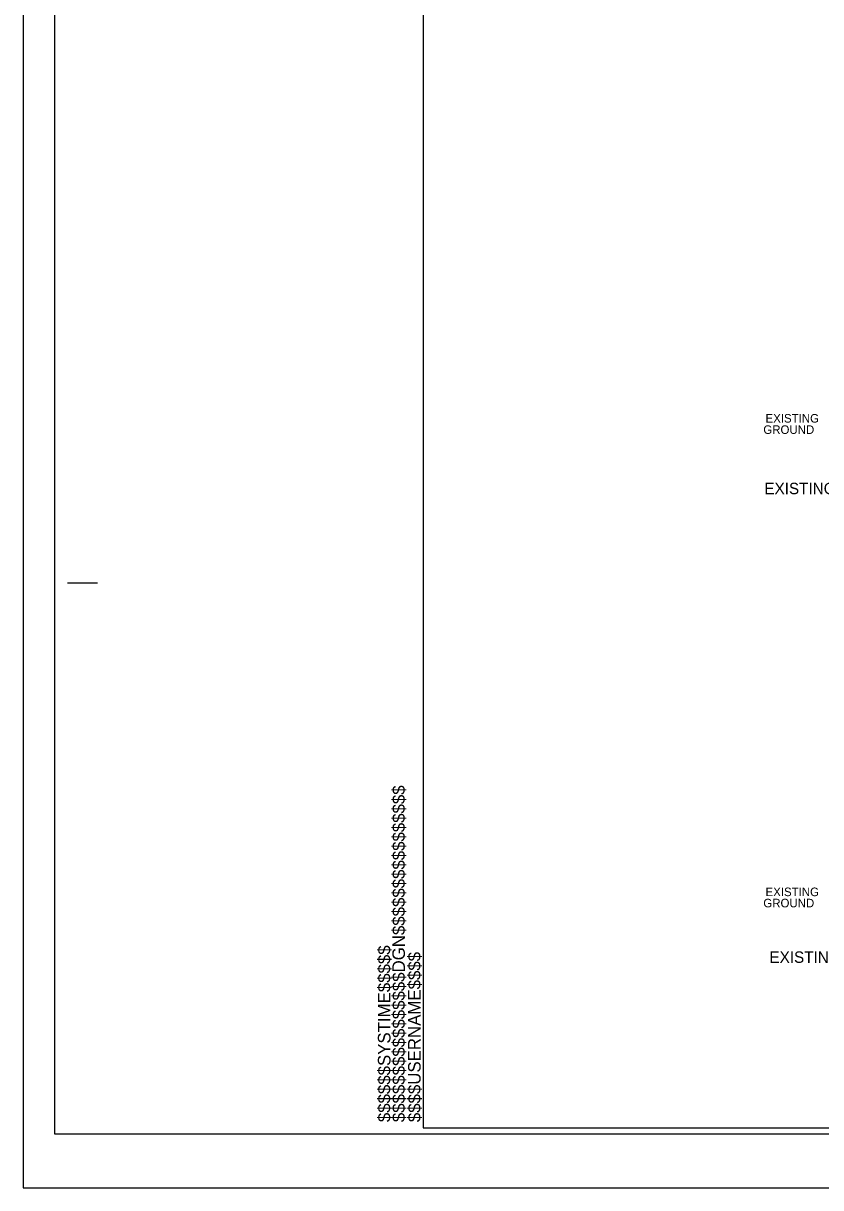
# Model space of a CAD drawing. Extents: x 1022283 to 1026986, y 174822 to 180471.
# Drawn here: x 1022283 to 1023116, y 177721 to 178936 of the extents above; entities that cross this region are included whole.
import ezdxf

# ---------------------------------------------------------------- set-up
doc = ezdxf.new("R2010")
doc.units = 0
for name, color, linetype in [('Sheet Cutting Line CELL', 7, 'Continuous'), ('Sheet Plot Border Inside CELL', 7, 'Continuous'), ('Sheet Plot Border Outside CELL', 7, 'Continuous'), ('Sheet Typical CELL', 7, 'Continuous'), ('Typical Slope Point Local CELL', 7, 'Continuous'), ('Typical Text General CELL', 7, 'Continuous')]:
    doc.layers.add(name, color=color, linetype=linetype)

msp = doc.modelspace()

# ---------------------------------------------------------------- linework, layer by layer
at = {"layer": 'Sheet Cutting Line CELL'}
for p, q in [((1022283.2, 180471.5), (1022283.2, 177721.5)), ((1022283.2, 177721.5), (1026493.2, 177721.5))]:
    msp.add_line(p, q, dxfattribs=at)
at = {"layer": 'Sheet Plot Border Inside CELL'}
msp.add_lwpolyline([(1026482, 180415.4), (1022315.7, 180415.4), (1022315.7, 177777.6), (1026482, 177777.6)], close=True, dxfattribs=at)
at = {"layer": 'Sheet Plot Border Outside CELL'}
msp.add_lwpolyline([(1026493.2, 180471.5), (1022283.2, 180471.5), (1022283.2, 177721.5), (1026493.2, 177721.5)], close=True, dxfattribs=at)
at = {"layer": 'Sheet Typical CELL'}
for p, q in [((1022329.5, 178352.7), (1022360.7, 178352.7)), ((1022700.7, 177784), (1022700.7, 177784)), ((1022700.7, 177784), (1022700.7, 177784)), ((1022700.7, 177784), (1022700.7, 177784)), ((1022700.7, 177784), (1022700.7, 177784)), ((1022700.7, 177784), (1022700.7, 177784)), ((1022700.7, 177784), (1022700.7, 177784))]:
    msp.add_line(p, q, dxfattribs=at)
msp.add_lwpolyline([(1026450.7, 180409), (1022700.7, 180409), (1022700.7, 177784), (1026450.7, 177784)], close=True, dxfattribs=at)
msp.add_lwpolyline([(1022794.5, 177784), (1022794.5, 177784)], dxfattribs=at)

# ---------------------------------------------------------------- texts
for s, p in [('$$$$$$$$$$$$$$$$DGN$$$$$$$$$$$$$$$$', (1022681.6, 177789.9)), ('$$$$$$SYSTIME$$$$$', (1022666.5, 177789.9)), ('$$$$USERNAME$$$$', (1022698, 177789.9))]:
    msp.add_text(s, height=13.125, rotation=90, dxfattribs=at).set_placement(p)
at = {"layer": 'Typical Slope Point Local CELL'}
for s, p in [('EXISTING ', (1023058, 178519.8)), ('EXISTING ', (1023058, 178519.8)), ('GROUND', (1023055.7, 178508)), ('GROUND', (1023055.7, 178508)), ('EXISTING ', (1023058, 178025.7)), ('EXISTING ', (1023058, 178025.7)), ('GROUND', (1023055.7, 178014)), ('GROUND', (1023055.7, 178014))]:
    msp.add_text(s, height=8.94, dxfattribs=at).set_placement(p)
at = {"layer": 'Typical Text General CELL'}
for p in [(1023056.8, 178445.1), (1023062.1, 177956.1)]:
    msp.add_text('EXISTING SIDEWALK', height=11.898, dxfattribs=at).set_placement(p)

doc.saveas('drawing.dxf')
